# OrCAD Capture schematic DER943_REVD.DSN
size D; title: DER-943; rev: C
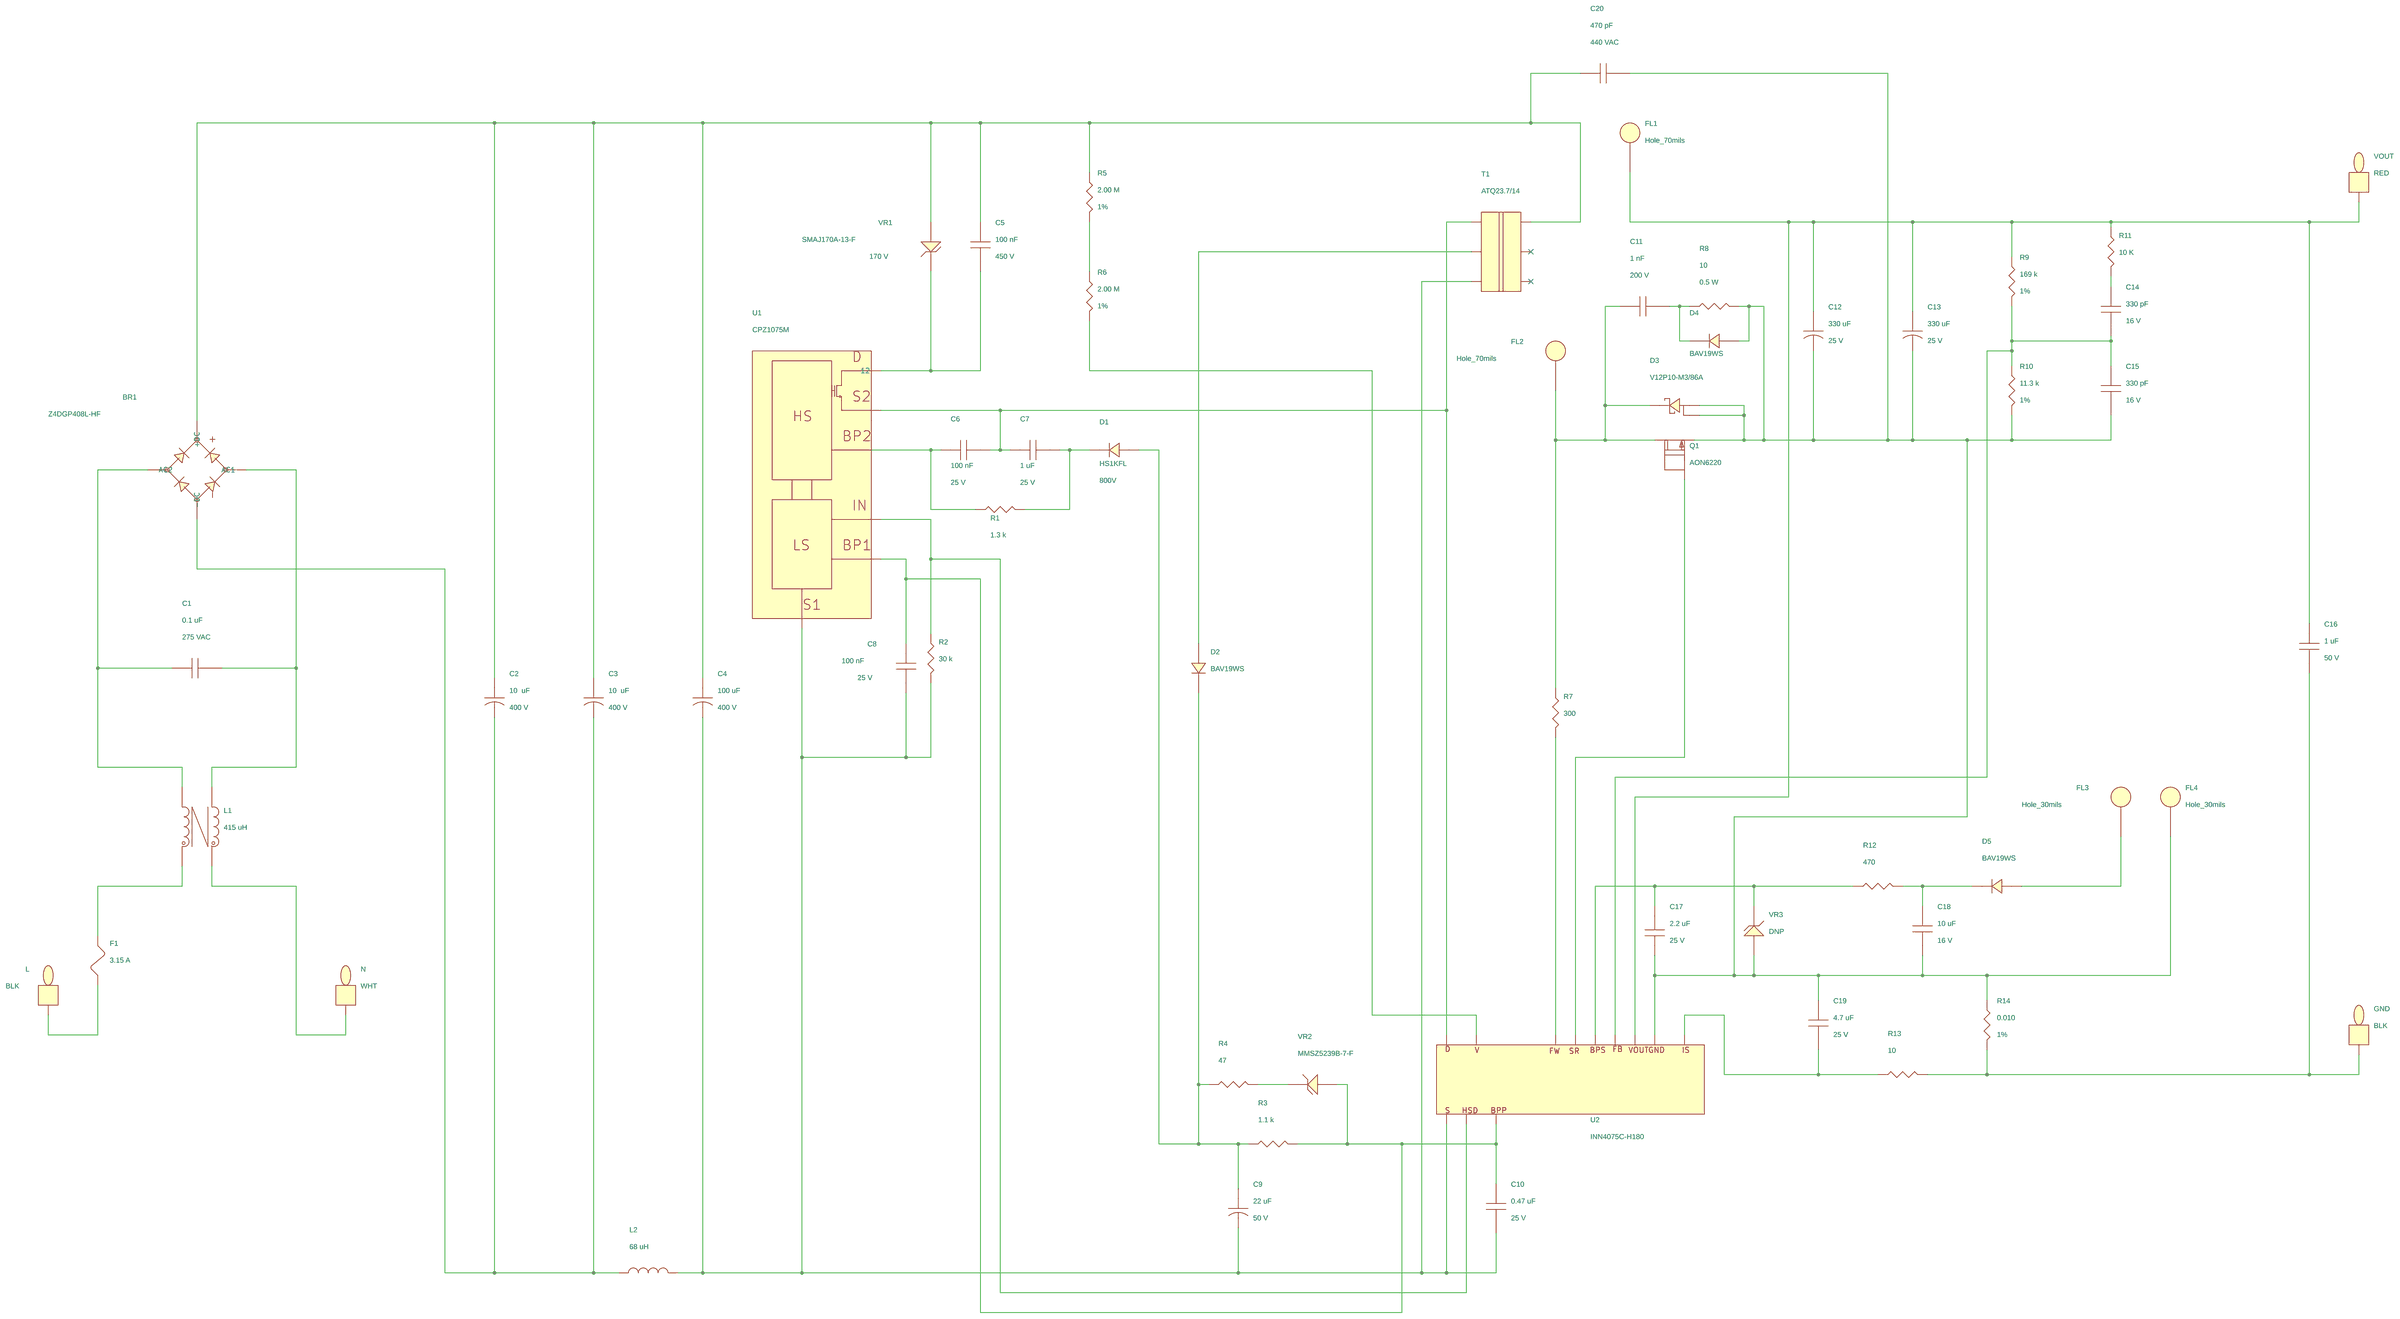
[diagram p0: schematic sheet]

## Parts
BR1  Z4DGP408L-HF  [pi_sm_d_z4d]
C1  0.1 uF  [pinpxcaprad13x6x12p1mm040]
C2  10  uF  [PI_POLCAPD8mmxlLS3p5mm063V]
C3  10  uF  [PI_POLCAPD8mmxlLS3p5mm063V]
C4  100 uF  [pipolcapclyd500ls200040]
C5  100 nF  [pismc1206]
C6  100 nF  [pismc0603]
C7  1 uF  [pismc0805]
C8  100 nF  [pismc0603]
C9  22 uF  [pipolcapclyd200ls80030]
C10  0.47 uF  [pismc0805]
C11  1 nF  [pismc0805]
C12  330 uF  [pipolcapcyld315ls138d030]
C13  330 uF  [pipolcapcyld315ls138d030]
C14  330 pF  [pismr0402]
C15  330 pF  [pismr0402]
C16  1 uF  [pismc0805]
C17  2.2 uF  [pismc0805]
C18  10 uF  [pismc0805]
C19  4.7 uF  [pismc0603]
C20  470 pF  [pinpcaprad7p5x11p5ls7p5mm030]
D1  HS1KFL  [pi_sm_sod-123_12]
D2  BAV19WS  [pismsod323]
D3  V12P10-M3/86A  [pi_sm_d_to-277a]
D4  BAV19WS  [pismsod323]
D5  BAV19WS  [pismsod323]
F1  3.15 A  [pi_rst_microfuse]
FL1  Hole_70mils  [pi_hole_70mil]
FL2  Hole_70mils  [pi_hole_70mil]
FL3  Hole_30mils  [pi_hole_30mil]
FL4  Hole_30mils  [pi_hole_30mil]
GND  BLK  [pitpkeystone100x100]
L  BLK  [pitpkeystone100x100]
L1  415 uH  [pi_toroid_CMC4p_V_275uH]
L2  68 uH  [pi2p14Dx6mmWd060]
N  WHT  [pitpkeystone100x100]
Q1  AON6220  [pismpqfn5x6b]
R1  1.3 k  [pismr0603]
R2  30 k  [pismr0402]
R3  1.1 k  [pismr0603]
R4  47  [pismr0603]
R5  2.00 M  [pismr1206]
R6  2.00 M  [pismr1206]
R7  300  [pismr0603]
R8  10  [pi12wvresd180ls150d040]
R9  169 k  [pismr0603]
R10  11.3 k  [pismr0402]
R11  10 K  [pismr0402]
R12  470  [pismr0603]
R13  10  [pismr0603]
R14  0.010  [pismr0805]
T1  ATQ23.7/14  [pi_bobbin_ATQ23_7_H_6P]
U1  CPZ1075M  [PI_SM_MinSOP16A_1]
U2  INN4075C-H180  [pi_ic_insop_24d_IPC]
VOUT  RED  [pitpkeystone100x100]
VR1  SMAJ170A-13-F  [pismdo214ac12]
VR2  MMSZ5239B-7-F  [pi_sm_sod-123_12]
VR3  DNP  [pi_sm_sod-123_12]

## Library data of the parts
BR1 = DISCRETE_BRIDGE_+~~-: Part Number: 15-01113-00
C1 = CAP_NP: ALT_SYMBOLS: pinpxcaprad13x6x12p1mm040H; Disp_Voltage: 275 VAC; FPLIST: pinpxcaprad13x6x12p1mm040,pinpxcaprad13x6x12p1mm040H; Part Number: 20-01691-00; Voltage: 275 VAC
C2 C3 = CAP_POL: Disp_Voltage: 400 V; FPLIST: PI_POLCAPD8xH11xlLS3p5mm063H,PI_POLCAPD8mmxlLS3p5mm063V; Part Number: 20-09025-00; Voltage: 400 V
C4 = CAP_POL: ALT_SYMBOLS: pipolcapclyd500ls2000401650lh; Disp_Voltage: 400 V; FPLIST: pipolcapclyd500ls200040,pipolcapclyd500ls2000401650lh; Part Number: 20-01653-00; Voltage: 400 V
C5 = CAP_NP: Disp_Voltage: 450 V; Part Number: 20-08695-00; Voltage: 450 V
C6 C8 = CAP_NP: Disp_Voltage: 25 V; Part Number: 20-00528-00; Voltage: 25 V
C7 = CAP_NP: Disp_Voltage: 25 V; Part Number: 20-09171-00; Voltage: 25 V
C9 = CAP_POL: ALT_SYMBOLS: pipolcapclyd200ls80030h; Disp_Voltage: 50 V; FPLIST: pipolcapclyd200ls80030,pipolcapclyd200ls80030h; Part Number: 20-00056-00; Voltage: 50 V
C10 = CAP_NP: Disp_Voltage: 25 V; Part Number: 20-09182-00; Voltage: 25 V
C11 = CAP_NP: ALT_SYMBOLS: pismc0805_1; Disp_Voltage: 200 V; FPLIST: pismc0805,pismc0805_1; Part Number: 20-00737-00; Voltage: 200 V
C12 C13 = CAP_POL: ALT_SYMBOLS: pipolcapcyld315ls138d030h; Disp_Voltage: 25 V; FPLIST: pipolcapcyld315ls138d030,pipolcapcyld315ls138d030h; Part Number: 20-09107-00; Voltage: 25 V
C14 C15 = CAP_NP: ALT_SYMBOLS: pismr0402_1; Disp_Voltage: 16 V; FPLIST: pismr0402,pismr0402_1; Part Number: 20-08910-00; Voltage: 16 V
C16 = CAP_NP: Disp_Voltage: 50 V; Part Number: 20-00853-00; Voltage: 50 V
C17 = CAP_NP: Disp_Voltage: 25 V; Part Number: 20-01529-00; Voltage: 25 V
C18 = CAP_NP: Disp_Voltage: 16 V; Part Number: 20-08964-00; Voltage: 16 V
C19 = CAP_NP: Disp_Voltage: 25 V; Part Number: 20-01602-00; Voltage: 25 V
C20 = CAP_NP: Disp_Voltage: 440 VAC; Part Number: 20-01338-00; Voltage: 440 VAC
D1 = DIODE: Disp_Voltage: 800V; Part Number: 15-01686-00
D2 D4 D5 = DIODE: Part Number: 15-00658-00
D3 = DIODE_SCHOTTKY_TO-277A: Part Number: 15-00879-00
F1 = FUSE: ALT_SYMBOLS: pirstmicrofusehoz; FPLIST: pi_rst_microfuse,pirstmicrofusehoz; Part Number: 40-00020-00
FL1 FL2 = FlyingLead: Part Number: 35-00282-00
FL3 FL4 = FlyingLead: Part Number: 35-00284-00
GND L = TESTPOINT: ALT_SYMBOLS: TP_TH_CR2_D1_1; FPLIST: pitpkeystone100x100,TP_TH_CR2_D1_1; Part Number: 35-00079-00
L1 = TORRID_4P_12_34: ALT_SYMBOLS: pi_toroid_CMC4p_V,pi_toroid_CMC4p_V_275uH; FPLIST: pi_toroid_CMC4p_H,pi_toroid_CMC4p_V,pi_toroid_CMC4p_V_275uH; Part Number: 32-00412-00
L2 = INDUCTOR: Part Number: 32-00411-00
N = TESTPOINT: Part Number: 35-00081-00
Q1 = FET_N_SGD_123_4_5678: Part Number: 50-00276-00
R1 = R: Part Number: 05-01691-00
R2 = R: Part Number: 05-06246-00
R3 = R: Part Number: 05-01689-00
R4 = R: ALT_SYMBOLS: pismr0603_1; FPLIST: pismr0603,pismr0603_1; Part Number: 05-01656-00
R5 R6 = R: Disp_Tol: 1%; Part Number: 05-03156-00
R7 = R: Part Number: 05-01675-00
R8 = R: ALT_SYMBOLS: pi12wvresd180ls200d040,pi12wvresd180ls250d040,pi12wresd180ls675d040; Disp_Power: 0.5 W; FPLIST: pi12wvresd180ls150d040,pi12wvresd180ls200d040,pi12wvresd180ls250d040,pi12wresd180ls675d040; Part Number: 05-02627-00
R9 = R: Disp_Tol: 1%; Part Number: 05-01196-00
R10 = R: Disp_Tol: 1%; Part Number: 05-05940-00
R11 = R: Part Number: 05-03488-00
R12 = R: Part Number: 05-01680-00
R13 = R: Part Number: 05-01640-00
R14 = R: Disp_Tol: 1%; Part Number: 05-06574-00
T1 = BATQ23_7_6P_GENERIC: FPLIST: pi_bobbin_ATQ23_7_H_4P,pi_bobbin_ATQ23_7_H_6P; Part Number: 25-01171-00
U1 = ClampZeroMinSOP16: Part Number: 10-01330-00
U2 = MinnoPriSecCZ: ALT_SYMBOLS: pi_ic_insop_24d,PI_IC_INSOP24B; FPLIST: pi_ic_insop_24d_IPC, pi_ic_insop_24d,PI_IC_INSOP24B; Part Number: 10-01438-00
VOUT = TESTPOINT: Part Number: 35-00080-00
VR1 = DIODE_ZENER: Disp_Voltage: 170 V; Part Number: 15-01702-00
VR2 = DIODE_ZENER: Part Number: 15-01087-00
VR3 = DIODE_ZENER: Part Number: 15-01081-00

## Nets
N12670317: BR1.2(AC1) C1.2 L1.4
N12670400: BR1.3(AC2) C1.1 L1.2
N12670412: BR1.4(-DC) C2.2 C3.2 L2.1
N12670895: F1.2 L1.1
N12670899: L1.3 N.1
N12670957: F1.1 L.1
N12672041: BR1.1(+DC) C2.1 C3.1 C4.1 C5.1 C20.1 R5.1 T1.6 VR1.2
N12672408: C4.2 C8.2 C9.2 C10.2 L2.2 R2.2 T1.3 U1.3 U2.16
N12673168: C5.2 U1.16(12) VR1.1
N12673753: C6.2 C7.1 T1.1 U1.10 U2.24
N12673894: C7.2 D1.1 R1.2
N12673924: C6.1 R1.1 U1.9
N12674067: C8.1 C10.1 R3.2 U1.8 U2.14 VR2.2
N12674079: R2.1 U1.7 U2.15
N12675426: R4.2 VR2.1
N12675537: C9.1 D1.2 D2.1 R3.1 R4.1
N12675653: R6.2 U2.13
N12677294: D2.2 T1.2
N12679725: R5.2 R6.1
N12683607: R7.2 U2.7
N12683655: C12.1 C13.1 C16.1 FL1.1 R9.1 R11.1 U2.6 VOUT.1
N12683824: Q1.4(G) U2.5
N12683873: C11.1 D3.3(Cathode) FL2.1 Q1.5(D) R7.1
N12684085: C12.2 C13.2 C15.2 C17.1 C18.2 C19.1 C20.2 D3.1(A1) D3.2(A2) D4.2 FL4.1 Q1.1(S) R8.2 R10.2 R14.1 U2.2 VR3.2
N12684571: C11.2 D4.1 R8.1
N12685741: C14.2 C15.1 R9.2 R10.1 U2.3
N12685823: C14.1 R11.2
N12687150: C17.2 R12.1 U2.4 VR3.1
N12687458: C18.1 D5.1 R12.2
N12687556: D5.2 FL3.1
N12687728: C19.2 R13.1 U2.1
N12688309: C16.2 GND.1 R13.2 R14.2

Not connected (* = marked no-connect by the designer): Q1 2(S2) 3(S3) 6(D6) 7(D7) 8(D8); T1 4* 5*; U1 1 2 4 5 6 11
